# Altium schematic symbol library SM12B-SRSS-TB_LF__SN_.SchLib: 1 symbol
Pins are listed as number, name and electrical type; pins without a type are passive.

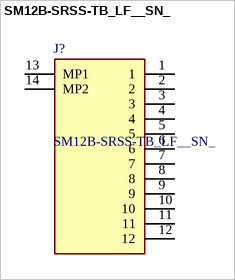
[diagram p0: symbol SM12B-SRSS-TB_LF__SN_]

## SM12B-SRSS-TB_LF__SN_
designator J?
Connector Header Surface Mount, Right Angle 12 position 0.039" (1.00mm); Manufacturer_Name: JST (JAPAN SOLDERLESS TERMINALS); Manufacturer_Part_Number: SM12B-SRSS-TB(LF)(SN); Geometry.Height: 2.95mm
footprint SM12BSRSSTBLFSN
pins: 1, 2, 3, 4, 5, 6, 7, 8, 9, 10, 11, 12, 13 MP1, 14 MP2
